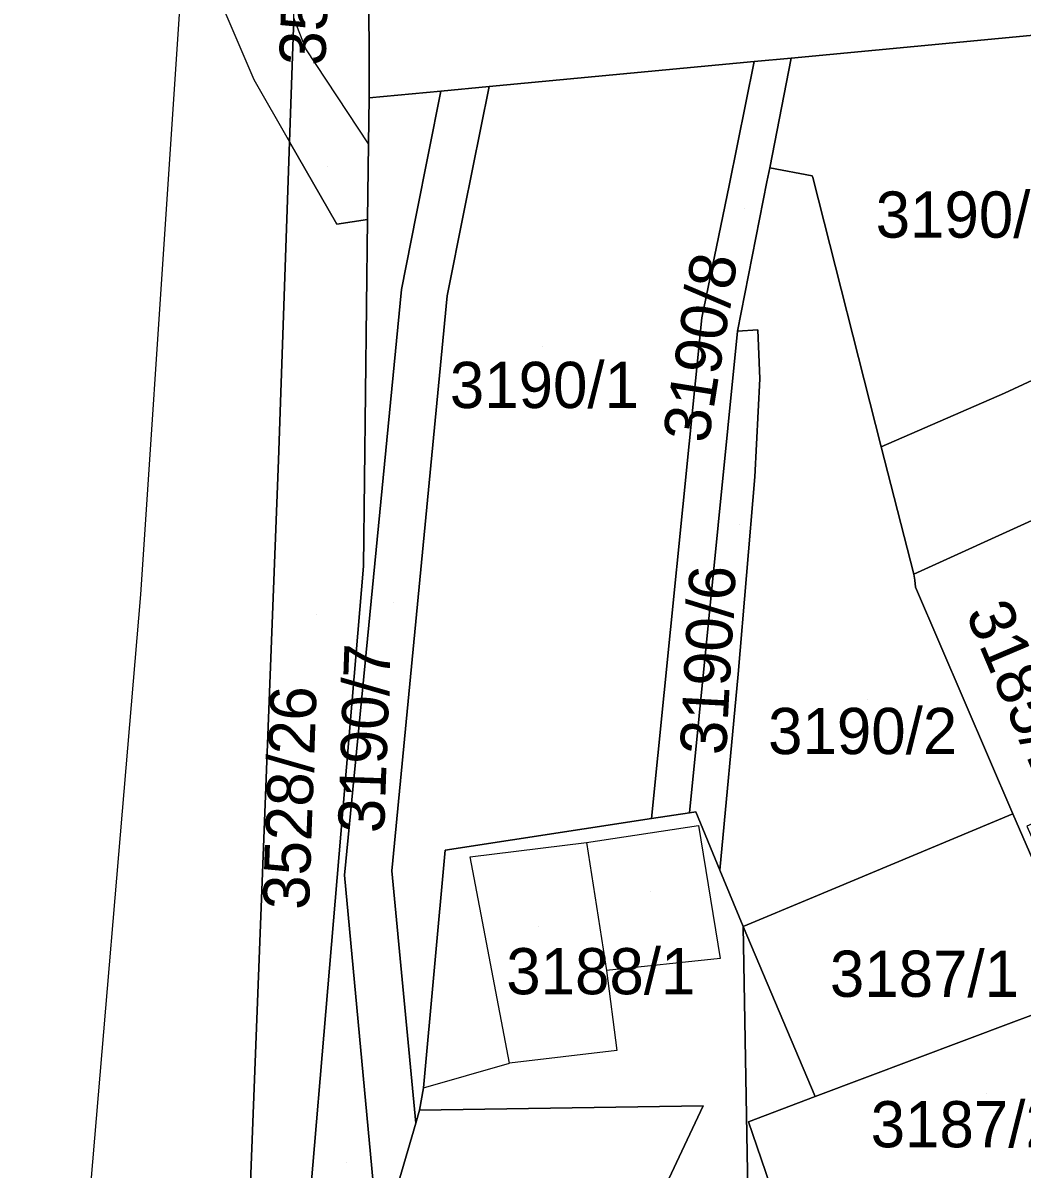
# Model space of a CAD drawing. Extents: x -262657 to -261595, y -1238015 to -1237156.
# Drawn here: x -262001.23 to -261958.02, y -1237946.95 to -1237897.37 of the extents above; entities that cross this region are included whole.
import ezdxf

# ---------------------------------------------------------------- set-up
doc = ezdxf.new("R2010")
doc.units = 0
for name, color, linetype in [('body_kn', 7, 'Continuous'), ('kladpar_druhypozemkov', 7, 'Continuous'), ('kladpar_hranice', 7, 'Continuous'), ('kladpar_parcelnecisla', 7, 'Continuous'), ('kladpar_plochy', 7, 'Continuous'), ('zappar_hrandruhpozemk', 7, 'Continuous')]:
    doc.layers.add(name, color=color, linetype=linetype)

msp = doc.modelspace()

# ---------------------------------------------------------------- linework, layer by layer
at = {"layer": 'body_kn'}
for p, q in [((-261989, -1237898.49), (-261989, -1237898.49)), ((-261969.6, -1237899.04), (-261969.6, -1237899.04)), ((-261969.6, -1237899.04), (-261969.6, -1237899.04)), ((-261968, -1237898.89), (-261968, -1237898.89)), ((-261991.25, -1237899.82), (-261991.25, -1237899.82)), ((-261983.15, -1237900.32), (-261983.15, -1237900.32)), ((-261983.15, -1237900.32), (-261983.15, -1237900.32)), ((-261981.07, -1237900.12), (-261981.07, -1237900.12)), ((-261986.26, -1237900.61), (-261986.26, -1237900.61)), ((-261986.26, -1237900.61), (-261986.26, -1237900.61)), ((-261989.7, -1237902.51), (-261989.7, -1237902.51)), ((-261989.7, -1237902.51), (-261989.7, -1237902.51)), ((-261986.29, -1237902.6), (-261986.29, -1237902.6)), ((-261986.29, -1237902.6), (-261986.29, -1237902.6)), ((-261968.93, -1237903.64), (-261968.93, -1237903.64)), ((-261967.09, -1237903.99), (-261967.09, -1237903.99)), ((-261970.69, -1237904.4), (-261970.69, -1237904.4)), ((-261969.05, -1237904.24), (-261969.05, -1237904.24)), ((-261967.07, -1237904.05), (-261967.07, -1237904.05)), ((-261982.14, -1237905.48), (-261982.14, -1237905.48)), ((-261986.33, -1237905.88), (-261986.33, -1237905.88)), ((-261984.22, -1237905.68), (-261984.22, -1237905.68)), ((-261987.65, -1237906.07), (-261987.65, -1237906.07)), ((-261984.86, -1237908.9), (-261984.86, -1237908.9)), ((-261982.88, -1237909.18), (-261982.88, -1237909.18)), ((-261971.86, -1237910.12), (-261971.86, -1237910.12)), ((-261971.86, -1237910.12), (-261971.86, -1237910.12)), ((-261970.33, -1237910.71), (-261970.33, -1237910.71)), ((-261970.33, -1237910.71), (-261970.33, -1237910.71)), ((-261969.44, -1237910.65), (-261969.44, -1237910.65)), ((-261969.36, -1237912.77), (-261969.36, -1237912.77)), ((-261958.77, -1237913.38), (-261958.77, -1237913.38)), ((-261964.11, -1237915.71), (-261964.11, -1237915.71)), ((-261990.17, -1237916.28), (-261990.17, -1237916.28)), ((-261969.57, -1237917.01), (-261969.57, -1237917.01)), ((-261986.5, -1237920.87), (-261986.5, -1237920.87)), ((-261962.7, -1237921.21), (-261962.7, -1237921.21)), ((-261962.66, -1237921.47), (-261962.66, -1237921.47)), ((-261962.62, -1237921.78), (-261962.62, -1237921.78)), ((-261996.13, -1237922.1), (-261996.13, -1237922.1)), ((-261970.29, -1237925.54), (-261970.29, -1237925.54)), ((-261972.4, -1237931.54), (-261972.4, -1237931.54)), ((-261972.13, -1237931.5), (-261972.13, -1237931.5)), ((-261958.41, -1237931.59), (-261958.41, -1237931.59)), ((-261974.05, -1237931.79), (-261974.05, -1237931.79)), ((-261972.01, -1237932.09), (-261972.01, -1237932.09)), ((-261972.01, -1237932.09), (-261972.01, -1237932.09)), ((-261982.97, -1237933.16), (-261982.97, -1237933.16)), ((-261976.86, -1237932.82), (-261976.86, -1237932.82)), ((-261976.86, -1237932.82), (-261976.86, -1237932.82)), ((-261981.89, -1237933.44), (-261981.89, -1237933.44)), ((-261987.32, -1237934.24), (-261987.32, -1237934.24)), ((-261985.28, -1237934.05), (-261985.28, -1237934.05)), ((-261971.09, -1237934.02), (-261971.09, -1237934.02)), ((-261967.03, -1237935.19), (-261967.03, -1237935.19)), ((-261967.03, -1237935.19), (-261967.03, -1237935.19)), ((-261970.08, -1237936.46), (-261970.08, -1237936.46)), ((-261970.08, -1237936.46), (-261970.08, -1237936.46)), ((-261971.08, -1237937.84), (-261971.08, -1237937.84)), ((-261975.99, -1237938.36), (-261975.99, -1237938.36)), ((-261958.37, -1237940.58), (-261958.37, -1237940.58)), ((-261975.54, -1237941.82), (-261975.54, -1237941.82)), ((-261975.54, -1237941.82), (-261975.54, -1237941.82)), ((-261980.19, -1237942.37), (-261980.19, -1237942.37)), ((-261980.19, -1237942.37), (-261980.19, -1237942.37)), ((-261983.9, -1237943.43), (-261983.9, -1237943.43)), ((-261983.9, -1237943.43), (-261983.9, -1237943.43)), ((-261966.96, -1237943.81), (-261966.96, -1237943.81)), ((-261984.08, -1237944.4), (-261984.08, -1237944.4)), ((-261971.81, -1237944.21), (-261971.81, -1237944.21)), ((-261984.24, -1237944.96), (-261984.24, -1237944.96)), ((-261969.85, -1237944.9), (-261969.85, -1237944.9)), ((-261969.85, -1237944.9), (-261969.85, -1237944.9))]:
    msp.add_line(p, q, dxfattribs=at)
at = {"layer": 'kladpar_druhypozemkov'}
for p, q in [((-261988.06, -1237903.6), (-261988.06, -1237903.6)), ((-261959.56, -1237904.83), (-261959.56, -1237904.83)), ((-261970.02, -1237905.4), (-261970.02, -1237905.4)), ((-261978.74, -1237911.38), (-261978.74, -1237911.38)), ((-261970.24, -1237919.07), (-261970.24, -1237919.07)), ((-261985.21, -1237922.43), (-261985.21, -1237922.43)), ((-261988.54, -1237922.94), (-261988.54, -1237922.94)), ((-261964.72, -1237926.63), (-261964.72, -1237926.63)), ((-261974.1, -1237934.94), (-261974.1, -1237934.94)), ((-261978.93, -1237936.45), (-261978.93, -1237936.45)), ((-261962.02, -1237937.55), (-261962.02, -1237937.55)), ((-261959.56, -1237943.69), (-261959.56, -1237943.69)), ((-261987.23, -1237946.65), (-261987.23, -1237946.65))]:
    msp.add_line(p, q, dxfattribs=at)
at = {"layer": 'kladpar_hranice'}
for points in [[(-261987.36, -1237844.03), (-261987.14, -1237847.02), (-261987.01, -1237865.75), (-261987.42, -1237876.92), (-261986.24, -1237891.44), (-261986.27, -1237894.41), (-261986.27, -1237894.84), (-261986.26, -1237900.61), (-261986.29, -1237902.6), (-261986.33, -1237905.88), (-261987.65, -1237906.07), (-261989.7, -1237902.51), (-261989.52, -1237897.17), (-261989.03, -1237883.09), (-261988.4, -1237868.65), (-261987.35, -1237844.34), (-261987.36, -1237844.03)], [(-261950.75, -1237864.05), (-261950.86, -1237867.45), (-261950.68, -1237874.14), (-261950.25, -1237879.91), (-261950.23, -1237882.83), (-261949.03, -1237897.48), (-261947.2, -1237908.87), (-261946.69, -1237912.11), (-261946.23, -1237914.53), (-261952.65, -1237917.01), (-261952.83, -1237916.63), (-261957, -1237918.63), (-261957.28, -1237918.75), (-261962.7, -1237921.21), (-261964.11, -1237915.71), (-261958.77, -1237913.38), (-261954.95, -1237911.61), (-261952.49, -1237909.16), (-261953.17, -1237902.73), (-261953.72, -1237897.54), (-261950.71, -1237897.26)], [(-261986.26, -1237900.61), (-261986.27, -1237894.84), (-261980.09, -1237894.42), (-261975.16, -1237894.06), (-261974.99, -1237896.13), (-261968.03, -1237895.52), (-261966.86, -1237895.49), (-261967.1, -1237892.49), (-261968.3, -1237892.56), (-261969.22, -1237884.42), (-261962.37, -1237883.78), (-261962.75, -1237881.1), (-261955.27, -1237880.43), (-261952.76, -1237880.2), (-261950.71, -1237897.26), (-261953.72, -1237897.54), (-261968, -1237898.89), (-261969.6, -1237899.04), (-261981.07, -1237900.12), (-261983.15, -1237900.32), (-261986.26, -1237900.61)], [(-261989.52, -1237897.17), (-261989.7, -1237902.51), (-261990.17, -1237916.28), (-261991.69, -1237955.34), (-261990.98, -1237971.5), (-261984.32, -1237979.25), (-261995.19, -1237979.22), (-261995.49, -1237985.74), (-261995.78, -1237991.95), (-261996, -1238000.09), (-262000.55, -1237999.73), (-262000.3, -1237996.58), (-261999.77, -1237990.05), (-262001.23, -1237982.42), (-261996.13, -1237922.1), (-261993.79, -1237887.01)], [(-261953.72, -1237897.54), (-261953.17, -1237902.73), (-261952.49, -1237909.16), (-261954.95, -1237911.61), (-261958.77, -1237913.38), (-261964.11, -1237915.71), (-261967.07, -1237904.05), (-261967.09, -1237903.99), (-261968.93, -1237903.64), (-261968, -1237898.89), (-261953.72, -1237897.54)], [(-261969.6, -1237899.04), (-261970.69, -1237904.4), (-261971.86, -1237910.12), (-261974.05, -1237931.79), (-261982.97, -1237933.16), (-261983.9, -1237943.43), (-261984.08, -1237944.4), (-261984.24, -1237944.96), (-261985.28, -1237934.05), (-261982.88, -1237909.18), (-261982.14, -1237905.48), (-261981.07, -1237900.12), (-261969.6, -1237899.04)], [(-261971.86, -1237910.12), (-261970.69, -1237904.4), (-261969.6, -1237899.04), (-261968, -1237898.89), (-261968.93, -1237903.64), (-261969.05, -1237904.24), (-261970.33, -1237910.71), (-261972.4, -1237931.54), (-261974.05, -1237931.79), (-261971.86, -1237910.12)], [(-261985.92, -1237949.25), (-261986.17, -1237951.57), (-261986.87, -1237953.97), (-261986.79, -1237954.72), (-261986.43, -1237954.71), (-261988.07, -1237969.83), (-261990.4, -1237967.07), (-261986.5, -1237920.87), (-261986.33, -1237905.88), (-261986.29, -1237902.6), (-261986.26, -1237900.61), (-261983.15, -1237900.32), (-261984.22, -1237905.68), (-261984.86, -1237908.9), (-261987.32, -1237934.24), (-261985.92, -1237949.25)], [(-261983.15, -1237900.32), (-261981.07, -1237900.12), (-261982.14, -1237905.48), (-261982.88, -1237909.18), (-261985.28, -1237934.05), (-261984.24, -1237944.96), (-261986.17, -1237951.57), (-261985.92, -1237949.25), (-261987.32, -1237934.24), (-261984.86, -1237908.9), (-261984.22, -1237905.68), (-261983.15, -1237900.32)], [(-261989.7, -1237902.51), (-261987.65, -1237906.07), (-261986.33, -1237905.88), (-261986.5, -1237920.87), (-261990.4, -1237967.07), (-261988.07, -1237969.83), (-261986.48, -1237971.71), (-261981.76, -1237977.31), (-261981.28, -1237979.18), (-261984.32, -1237979.25), (-261990.98, -1237971.5), (-261991.69, -1237955.34), (-261990.17, -1237916.28), (-261989.7, -1237902.51)], [(-261967.03, -1237935.19), (-261970.08, -1237936.46), (-261971.09, -1237934.02), (-261970.29, -1237925.54), (-261969.57, -1237917.01), (-261969.36, -1237912.77), (-261969.44, -1237910.65), (-261970.33, -1237910.71), (-261969.05, -1237904.24), (-261968.93, -1237903.64), (-261967.09, -1237903.99), (-261967.07, -1237904.05), (-261964.11, -1237915.71), (-261962.7, -1237921.21), (-261962.66, -1237921.47), (-261962.62, -1237921.78), (-261958.41, -1237931.59), (-261967.03, -1237935.19)], [(-261970.33, -1237910.71), (-261969.44, -1237910.65), (-261969.36, -1237912.77), (-261969.57, -1237917.01), (-261970.29, -1237925.54), (-261971.09, -1237934.02), (-261972.13, -1237931.5), (-261972.4, -1237931.54), (-261970.33, -1237910.71)], [(-261952.47, -1237929.74), (-261955.89, -1237931.26), (-261957.81, -1237932.11), (-261956.05, -1237936.09), (-261954.5, -1237935.4), (-261953.44, -1237937.78), (-261953.07, -1237937.62), (-261951.03, -1237942.23), (-261948.09, -1237940.97), (-261949.09, -1237938.59), (-261948.55, -1237938.34), (-261945.91, -1237944.31), (-261951.59, -1237946.87), (-261951.67, -1237946.72), (-261953.56, -1237942.59), (-261953.69, -1237942.29), (-261956.06, -1237936.99), (-261958.41, -1237931.59), (-261962.62, -1237921.78), (-261962.66, -1237921.47), (-261962.7, -1237921.21), (-261957.28, -1237918.75), (-261957.02, -1237919.34), (-261952.47, -1237929.74)], [(-261970.08, -1237936.46), (-261969.76, -1237954.42), (-261970.27, -1237954.42), (-261973.03, -1237954.43), (-261974.66, -1237954.44), (-261976.4, -1237954.45), (-261976.62, -1237954.45), (-261971.81, -1237944.21), (-261984.08, -1237944.4), (-261983.9, -1237943.43), (-261982.97, -1237933.16), (-261974.05, -1237931.79), (-261972.4, -1237931.54), (-261972.13, -1237931.5), (-261971.09, -1237934.02), (-261970.08, -1237936.46)], [(-261951.67, -1237946.72), (-261951.59, -1237946.87), (-261951.95, -1237947.03), (-261960.61, -1237950.64), (-261963.53, -1237951.87), (-261963.8, -1237951.23), (-261952.17, -1237946.79), (-261955.27, -1237939.42), (-261958.37, -1237940.58), (-261966.96, -1237943.81), (-261970.08, -1237936.46), (-261967.03, -1237935.19), (-261958.41, -1237931.59), (-261956.06, -1237936.99), (-261953.69, -1237942.29), (-261953.56, -1237942.59), (-261951.67, -1237946.72)], [(-261963.53, -1237951.87), (-261969.76, -1237954.42), (-261970.08, -1237936.46), (-261966.96, -1237943.81), (-261969.85, -1237944.9), (-261968.55, -1237948.7), (-261965.57, -1237947.68), (-261964.25, -1237951.4), (-261963.8, -1237951.23), (-261963.53, -1237951.87)], [(-261969.85, -1237944.9), (-261966.96, -1237943.81), (-261958.37, -1237940.58), (-261955.27, -1237939.42), (-261952.17, -1237946.79), (-261963.8, -1237951.23), (-261964.25, -1237951.4), (-261965.57, -1237947.68), (-261968.55, -1237948.7), (-261969.85, -1237944.9)], [(-261976.62, -1237954.45), (-261978.06, -1237954.49), (-261984.96, -1237954.67), (-261986.43, -1237954.71), (-261986.79, -1237954.72), (-261986.87, -1237953.97), (-261986.17, -1237951.57), (-261984.24, -1237944.96), (-261984.08, -1237944.4), (-261971.81, -1237944.21), (-261976.62, -1237954.45)]]:
    msp.add_lwpolyline(points, dxfattribs=at)
at = {"layer": 'kladpar_plochy'}
for points in [[(-261987.36, -1237844.03), (-261987.14, -1237847.02), (-261987.01, -1237865.75), (-261987.42, -1237876.92), (-261986.24, -1237891.44), (-261986.27, -1237894.41), (-261986.27, -1237894.84), (-261986.26, -1237900.61), (-261986.29, -1237902.6), (-261986.33, -1237905.88), (-261987.65, -1237906.07), (-261989.7, -1237902.51), (-261989.52, -1237897.17), (-261989.03, -1237883.09), (-261988.4, -1237868.65), (-261987.35, -1237844.34)], [(-261986.26, -1237900.61), (-261986.27, -1237894.84), (-261980.09, -1237894.42), (-261975.16, -1237894.06), (-261974.99, -1237896.13), (-261968.03, -1237895.52), (-261966.86, -1237895.49), (-261967.1, -1237892.49), (-261968.3, -1237892.56), (-261969.22, -1237884.42), (-261962.37, -1237883.78), (-261962.75, -1237881.1), (-261955.27, -1237880.43), (-261952.76, -1237880.2), (-261950.71, -1237897.26), (-261953.72, -1237897.54), (-261968, -1237898.89), (-261969.6, -1237899.04), (-261981.07, -1237900.12), (-261983.15, -1237900.32)], [(-261953.72, -1237897.54), (-261953.17, -1237902.73), (-261952.49, -1237909.16), (-261954.95, -1237911.61), (-261958.77, -1237913.38), (-261964.11, -1237915.71), (-261967.07, -1237904.05), (-261967.09, -1237903.99), (-261968.93, -1237903.64), (-261968, -1237898.89)], [(-261969.6, -1237899.04), (-261970.69, -1237904.4), (-261971.86, -1237910.12), (-261974.05, -1237931.79), (-261982.97, -1237933.16), (-261983.9, -1237943.43), (-261984.08, -1237944.4), (-261984.24, -1237944.96), (-261985.28, -1237934.05), (-261982.88, -1237909.18), (-261982.14, -1237905.48), (-261981.07, -1237900.12)], [(-261971.86, -1237910.12), (-261970.69, -1237904.4), (-261969.6, -1237899.04), (-261968, -1237898.89), (-261968.93, -1237903.64), (-261969.05, -1237904.24), (-261970.33, -1237910.71), (-261972.4, -1237931.54), (-261974.05, -1237931.79)], [(-261985.92, -1237949.25), (-261986.17, -1237951.57), (-261986.87, -1237953.97), (-261986.79, -1237954.72), (-261986.43, -1237954.71), (-261988.07, -1237969.83), (-261990.4, -1237967.07), (-261986.5, -1237920.87), (-261986.33, -1237905.88), (-261986.29, -1237902.6), (-261986.26, -1237900.61), (-261983.15, -1237900.32), (-261984.22, -1237905.68), (-261984.86, -1237908.9), (-261987.32, -1237934.24)], [(-261983.15, -1237900.32), (-261981.07, -1237900.12), (-261982.14, -1237905.48), (-261982.88, -1237909.18), (-261985.28, -1237934.05), (-261984.24, -1237944.96), (-261986.17, -1237951.57), (-261985.92, -1237949.25), (-261987.32, -1237934.24), (-261984.86, -1237908.9), (-261984.22, -1237905.68)], [(-261989.7, -1237902.51), (-261987.65, -1237906.07), (-261986.33, -1237905.88), (-261986.5, -1237920.87), (-261990.4, -1237967.07), (-261988.07, -1237969.83), (-261986.48, -1237971.71), (-261981.76, -1237977.31), (-261981.28, -1237979.18), (-261984.32, -1237979.25), (-261990.98, -1237971.5), (-261991.69, -1237955.34), (-261990.17, -1237916.28)], [(-261967.03, -1237935.19), (-261970.08, -1237936.46), (-261971.09, -1237934.02), (-261970.29, -1237925.54), (-261969.57, -1237917.01), (-261969.36, -1237912.77), (-261969.44, -1237910.65), (-261970.33, -1237910.71), (-261969.05, -1237904.24), (-261968.93, -1237903.64), (-261967.09, -1237903.99), (-261967.07, -1237904.05), (-261964.11, -1237915.71), (-261962.7, -1237921.21), (-261962.66, -1237921.47), (-261962.62, -1237921.78), (-261958.41, -1237931.59)], [(-261970.33, -1237910.71), (-261969.44, -1237910.65), (-261969.36, -1237912.77), (-261969.57, -1237917.01), (-261970.29, -1237925.54), (-261971.09, -1237934.02), (-261972.13, -1237931.5), (-261972.4, -1237931.54)], [(-261952.47, -1237929.74), (-261955.89, -1237931.26), (-261957.81, -1237932.11), (-261956.05, -1237936.09), (-261954.5, -1237935.4), (-261953.44, -1237937.78), (-261953.07, -1237937.62), (-261951.03, -1237942.23), (-261948.09, -1237940.97), (-261949.09, -1237938.59), (-261948.55, -1237938.34), (-261945.91, -1237944.31), (-261951.59, -1237946.87), (-261951.67, -1237946.72), (-261953.56, -1237942.59), (-261953.69, -1237942.29), (-261956.06, -1237936.99), (-261958.41, -1237931.59), (-261962.62, -1237921.78), (-261962.66, -1237921.47), (-261962.7, -1237921.21), (-261957.28, -1237918.75), (-261957.02, -1237919.34)], [(-261970.08, -1237936.46), (-261969.76, -1237954.42), (-261970.27, -1237954.42), (-261973.03, -1237954.43), (-261974.66, -1237954.44), (-261976.4, -1237954.45), (-261976.62, -1237954.45), (-261971.81, -1237944.21), (-261984.08, -1237944.4), (-261983.9, -1237943.43), (-261982.97, -1237933.16), (-261974.05, -1237931.79), (-261972.4, -1237931.54), (-261972.13, -1237931.5), (-261971.09, -1237934.02)], [(-261951.67, -1237946.72), (-261951.59, -1237946.87), (-261951.95, -1237947.03), (-261960.61, -1237950.64), (-261963.53, -1237951.87), (-261963.8, -1237951.23), (-261952.17, -1237946.79), (-261955.27, -1237939.42), (-261958.37, -1237940.58), (-261966.96, -1237943.81), (-261970.08, -1237936.46), (-261967.03, -1237935.19), (-261958.41, -1237931.59), (-261956.06, -1237936.99), (-261953.69, -1237942.29), (-261953.56, -1237942.59)], [(-261963.53, -1237951.87), (-261969.76, -1237954.42), (-261970.08, -1237936.46), (-261966.96, -1237943.81), (-261969.85, -1237944.9), (-261968.55, -1237948.7), (-261965.57, -1237947.68), (-261964.25, -1237951.4), (-261963.8, -1237951.23)], [(-261969.85, -1237944.9), (-261966.96, -1237943.81), (-261958.37, -1237940.58), (-261955.27, -1237939.42), (-261952.17, -1237946.79), (-261963.8, -1237951.23), (-261964.25, -1237951.4), (-261965.57, -1237947.68), (-261968.55, -1237948.7)], [(-261976.62, -1237954.45), (-261978.06, -1237954.49), (-261984.96, -1237954.67), (-261986.43, -1237954.71), (-261986.79, -1237954.72), (-261986.87, -1237953.97), (-261986.17, -1237951.57), (-261984.24, -1237944.96), (-261984.08, -1237944.4), (-261971.81, -1237944.21)]]:
    msp.add_lwpolyline(points, close=True, dxfattribs=at)
for points in [[(-261950.23, -1237882.83), (-261949.03, -1237897.48), (-261947.2, -1237908.87), (-261946.69, -1237912.11), (-261946.23, -1237914.53), (-261952.65, -1237917.01), (-261952.83, -1237916.63), (-261957, -1237918.63), (-261957.28, -1237918.75), (-261962.7, -1237921.21), (-261964.11, -1237915.71), (-261958.77, -1237913.38), (-261954.95, -1237911.61), (-261952.49, -1237909.16), (-261953.17, -1237902.73), (-261953.72, -1237897.54), (-261950.71, -1237897.26)], [(-261989.52, -1237897.17), (-261989.7, -1237902.51), (-261990.17, -1237916.28), (-261991.69, -1237955.34), (-261990.98, -1237971.5), (-261984.32, -1237979.25), (-261995.19, -1237979.22), (-261995.49, -1237985.74), (-261995.78, -1237991.95), (-261996, -1238000.09), (-262000.55, -1237999.73), (-262000.3, -1237996.58), (-261999.77, -1237990.05), (-262001.23, -1237982.42), (-261996.13, -1237922.1), (-261993.79, -1237887.01)]]:
    msp.add_lwpolyline(points, dxfattribs=at)
at = {"layer": 'zappar_hrandruhpozemk'}
for p, q in [((-261993.41, -1237894.73), (-261991.25, -1237899.82)), ((-261989, -1237898.49), (-261989.52, -1237897.17)), ((-261986.29, -1237902.6), (-261989, -1237898.49)), ((-261991.25, -1237899.82), (-261989.7, -1237902.51)), ((-261972.01, -1237932.09), (-261971.08, -1237937.84)), ((-261976.86, -1237932.82), (-261975.99, -1237938.36)), ((-261980.19, -1237942.37), (-261981.89, -1237933.44)), ((-261975.54, -1237941.82), (-261980.19, -1237942.37)), ((-261983.9, -1237943.43), (-261980.19, -1237942.37))]:
    msp.add_line(p, q, dxfattribs=at)
for points in [[(-261981.89, -1237933.44), (-261976.86, -1237932.82), (-261972.01, -1237932.09)], [(-261971.08, -1237937.84), (-261975.99, -1237938.36), (-261975.54, -1237941.82)]]:
    msp.add_lwpolyline(points, dxfattribs=at)

# ---------------------------------------------------------------- texts
at = {"layer": 'kladpar_parcelnecisla'}
for s, rotation, p in [('3528/25', 88, (-261988.153, -1237899.24)), ('3190/8', 81, (-261971.592, -1237915.598)), ('3190/6', 87, (-261970.821, -1237929.07)), ('3185/1', 293, (-261960.479, -1237922.896)), ('3190/7', 88, (-261985.609, -1237932.439)), ('3528/26', 88, (-261988.861, -1237935.754))]:
    msp.add_text(s, height=2, rotation=rotation, dxfattribs=at).set_placement(p)
for s, p in [('3190/3', (-261964.347, -1237906.66)), ('3190/1', (-261982.765, -1237914.03)), ('3190/2', (-261969.001, -1237929)), ('3188/1', (-261980.326, -1237939.39)), ('3187/1', (-261966.328, -1237939.5)), ('3187/2', (-261964.564, -1237946.01))]:
    msp.add_text(s, height=2, dxfattribs=at).set_placement(p)

doc.saveas('drawing.dxf')
